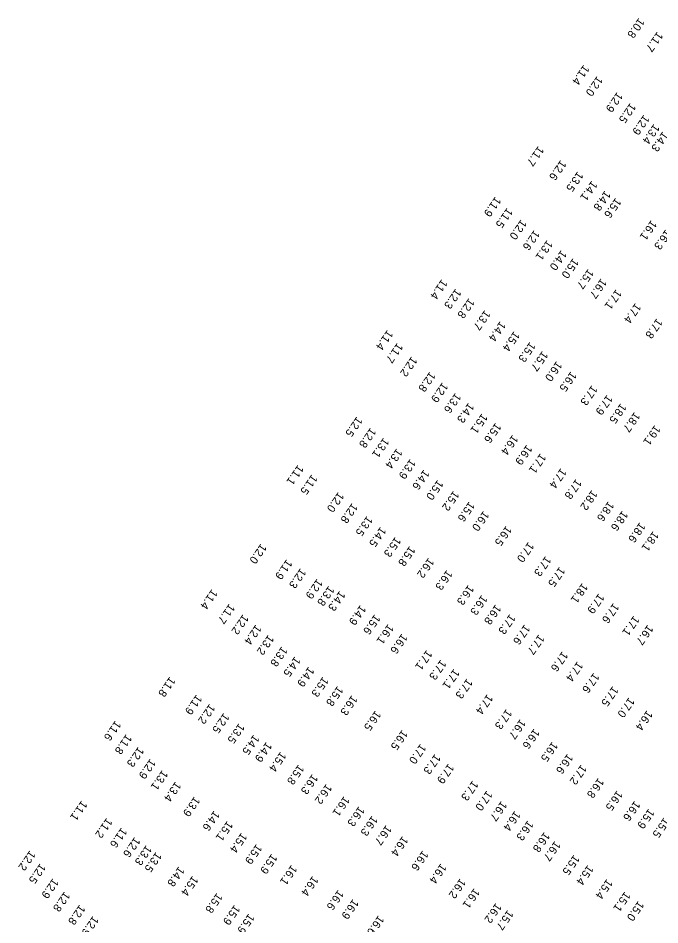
# Model space of a CAD drawing. Extents: x 815385 to 820851, y 582449 to 604245.
# Drawn here: x 816773 to 817174, y 584573 to 585139 of the extents above; entities that cross this region are included whole.
import ezdxf

# ---------------------------------------------------------------- set-up
doc = ezdxf.new("R2010")
doc.units = 0
doc.layers.add('V-TOPO-SOUN-101408', color=7, linetype='Continuous')

msp = doc.modelspace()

# ---------------------------------------------------------------- texts
at = {"layer": 'V-TOPO-SOUN-101408'}
for s, p in [('10.8 ', (817160.59, 585139.74)), ('11.7 ', (817172.12, 585131.14)), ('11.4 ', (817126.14, 585110.45)), ('12.0 ', (817134.56, 585103.43)), ('12.9 ', (817147.05, 585093.41)), ('12.5 ', (817155.23, 585086.61)), ('12.9 ', (817163.7, 585079.18)), ('13.4 ', (817170.03, 585073.49)), ('14.3 ', (817175.55, 585068.8)), ('11.7 ', (817097.75, 585059.69)), ('12.6 ', (817111.73, 585050.88)), ('13.5 ', (817122.34, 585043.79)), ('14.1 ', (817131.15, 585037.99)), ('11.9 ', (817070.92, 585028.06)), ('14.8 ', (817139.43, 585031.8)), ('15.6 ', (817146.06, 585027.28)), ('11.5 ', (817078.29, 585021.07)), ('12.0 ', (817086.97, 585013.75)), ('16.1 ', (817168.33, 585013.37)), ('12.6 ', (817095.2, 585007.17)), ('16.3 ', (817177.32, 585007.54)), ('13.1 ', (817103.24, 585000.89)), ('14.0 ', (817112.04, 584994.59)), ('15.0 ', (817119.48, 584989.57)), ('15.7 ', (817128.94, 584982.89)), ('11.4 ', (817037.46, 584976.47)), ('16.7 ', (817136.99, 584976.92)), ('12.3 ', (817046.1, 584970.55)), ('17.1 ', (817146.36, 584970.15)), ('12.8 ', (817054.4, 584964.56)), ('17.4 ', (817158.45, 584961.52)), ('13.7 ', (817064.33, 584957.14)), ('14.4 ', (817073.93, 584950.18)), ('17.8 ', (817171.85, 584951.97)), ('11.4 ', (817003.48, 584944.72)), ('15.4 ', (817082.62, 584943.95)), ('11.7 ', (817009.68, 584936.66)), ('15.3 ', (817092.5, 584937.22)), ('15.7 ', (817100.29, 584931.53)), ('12.2 ', (817018.59, 584928.15)), ('16.0 ', (817109.15, 584925.21)), ('12.8 ', (817030.01, 584918.65)), ('16.5 ', (817118.14, 584918.82)), ('12.9 ', (817037.85, 584911.97)), ('17.3 ', (817131.22, 584910.18)), ('13.6 ', (817045.99, 584905.37)), ('17.9 ', (817140.71, 584904.19)), ('14.3 ', (817054.15, 584899.25)), ('18.5 ', (817149.27, 584898.91)), ('15.1 ', (817062.55, 584892.55)), ('18.7 ', (817157.87, 584893.44)), ('12.5 ', (816984.36, 584890.6)), ('15.6 ', (817071.08, 584886.72)), ('12.8 ', (816992.92, 584883.66)), ('19.1 ', (817170.55, 584885.26)), ('13.1 ', (817001.07, 584877.37)), ('16.4 ', (817081.68, 584879.16)), ('13.4 ', (817009.3, 584870.67)), ('16.9 ', (817090.48, 584872.95)), ('13.9 ', (817017.72, 584864.13)), ('17.1 ', (817099.07, 584867.62)), ('11.1 ', (816947.62, 584860.42)), ('14.6 ', (817026.23, 584857.45)), ('17.4 ', (817111.86, 584858.35)), ('11.5 ', (816956.25, 584854.44)), ('17.8 ', (817121.33, 584851.6)), ('15.0 ', (817034.86, 584851.03)), ('12.0 ', (816972.82, 584843.44)), ('15.2 ', (817044.82, 584844.28)), ('18.2 ', (817131.2, 584844.68)), ('12.8 ', (816981.42, 584836.52)), ('15.6 ', (817054.57, 584837.49)), ('18.6 ', (817141.56, 584837.68)), ('16.0 ', (817063.53, 584831.65)), ('18.6 ', (817150.28, 584831.78)), ('13.5 ', (816990.77, 584828.52)), ('18.6 ', (817161.14, 584824.47)), ('14.5 ', (816999.18, 584821.75)), ('16.5 ', (817077.7, 584822.37)), ('18.1 ', (817169.52, 584818.98)), ('15.3 ', (817008.41, 584815.41)), ('17.0 ', (817091.55, 584812.15)), ('12.0 ', (816924.46, 584811.19)), ('15.8 ', (817017.38, 584809.69)), ('11.9 ', (816940.5, 584801.35)), ('16.2 ', (817029.16, 584802.32)), ('17.3 ', (817102.3, 584803.41)), ('12.3 ', (816949.16, 584795.8)), ('17.5 ', (817111.02, 584796.74)), ('12.9 ', (816959.53, 584789.22)), ('16.3 ', (817040.6, 584794.73)), ('13.8 ', (816966.8, 584784.81)), ('16.3 ', (817054.04, 584785.39)), ('18.1 ', (817125.23, 584786.57)), ('11.4 ', (816893.81, 584782.71)), ('14.3 ', (816973.64, 584781.68)), ('16.3 ', (817062.43, 584779.11)), ('17.9 ', (817135.49, 584780.03)), ('11.7 ', (816904.66, 584773.62)), ('14.9 ', (816986.56, 584772.84)), ('16.8 ', (817071.06, 584773.17)), ('17.6 ', (817144.73, 584774.06)), ('12.2 ', (816913.22, 584766.98)), ('15.6 ', (816995.53, 584767)), ('17.3 ', (817079.98, 584767.17)), ('16.1 ', (817003.89, 584760.9)), ('17.1 ', (817157.41, 584766.16)), ('12.4 ', (816921.24, 584760.59)), ('17.6 ', (817089.17, 584760.66)), ('16.7 ', (817166.08, 584760.45)), ('13.2 ', (816929.06, 584754.19)), ('16.6 ', (817012.52, 584754.95)), ('17.7 ', (817098.07, 584754.42)), ('13.8 ', (816937.49, 584746.92)), ('17.1 ', (817028, 584744.73)), ('17.6 ', (817112.76, 584743.87)), ('14.5 ', (816945.63, 584740.63)), ('17.3 ', (817036.77, 584738.63)), ('14.9 ', (816954.25, 584734.27)), ('17.1 ', (817045.05, 584732.93)), ('17.4 ', (817122.21, 584737.58)), ('11.8 ', (816867.47, 584728)), ('15.3 ', (816963.17, 584727.97)), ('17.3 ', (817053.19, 584726.86)), ('17.6 ', (817132.37, 584730.44)), ('15.8 ', (816972.34, 584722.23)), ('17.5 ', (817144.28, 584722.11)), ('11.9 ', (816884.15, 584716.85)), ('16.3 ', (816981.24, 584716.45)), ('17.4 ', (817065.9, 584717.09)), ('12.2 ', (816892.35, 584711.03)), ('17.0 ', (817154.4, 584715.09)), ('12.5 ', (816901.2, 584705.31)), ('16.5 ', (816995.97, 584706.88)), ('17.3 ', (817077.8, 584707.77)), ('16.4 ', (817165.67, 584707.01)), ('11.6 ', (816833.5, 584700.6)), ('13.5 ', (816910.72, 584698.9)), ('16.7 ', (817086.47, 584701.54)), ('16.5 ', (817012.69, 584694.8)), ('16.6 ', (817095.09, 584695.52)), ('11.8 ', (816840.31, 584692.11)), ('14.5 ', (816919.95, 584691.83)), ('14.9 ', (816927.81, 584687.24)), ('16.5 ', (817106.49, 584687.45)), ('12.3 ', (816847.83, 584684.19)), ('17.0 ', (817024.16, 584686.1)), ('12.9 ', (816855.26, 584676.71)), ('15.4 ', (816936.72, 584681.17)), ('17.3 ', (817033.2, 584679.72)), ('16.6 ', (817116.02, 584679.91)), ('15.8 ', (816947.92, 584673.13)), ('17.9 ', (817041.6, 584673.74)), ('17.2 ', (817124.54, 584673.08)), ('13.1 ', (816862.81, 584669.66)), ('16.3 ', (816956.54, 584667.12)), ('16.8 ', (817135.27, 584664.75)), ('13.4 ', (816871.07, 584662.5)), ('16.2 ', (816965.29, 584661.01)), ('17.3 ', (817056.73, 584663.12)), ('16.1 ', (816976.38, 584653.33)), ('17.0 ', (817065.59, 584656.86)), ('16.5 ', (817146.97, 584656.9)), ('11.1 ', (816812.42, 584650.63)), ('13.9 ', (816882.88, 584653.17)), ('16.7 ', (817074.67, 584650.32)), ('16.6 ', (817157.95, 584650.44)), ('14.6 ', (816895.18, 584644.3)), ('16.3 ', (816985.67, 584647.04)), ('16.4 ', (817083.1, 584644.17)), ('15.9 ', (817166.77, 584645.59)), ('11.2 ', (816828.07, 584639.77)), ('15.1 ', (816903.43, 584637.87)), ('16.3 ', (816993.89, 584641.12)), ('16.3 ', (817091.21, 584638.2)), ('15.5 ', (817176.29, 584639.97)), ('11.6 ', (816837.29, 584633.72)), ('15.4 ', (816912.26, 584630.54)), ('16.7 ', (817002.67, 584635.28)), ('16.8 ', (817101.49, 584630.95)), ('12.6 ', (816845.53, 584627.77)), ('16.4 ', (817012.92, 584628.39)), ('16.7 ', (817108.14, 584625.36)), ('12.2 ', (816780.04, 584619.4)), ('13.3 ', (816852.78, 584622.74)), ('15.9 ', (816921.64, 584623.42)), ('16.6 ', (817025.53, 584619.39)), ('13.5 ', (816858.9, 584618.47)), ('15.9 ', (816931.13, 584617.33)), ('15.5 ', (817120.03, 584616.69)), ('12.5 ', (816786.53, 584611.34)), ('14.8 ', (816873.13, 584609.43)), ('16.1 ', (816943.53, 584610.38)), ('16.4 ', (817036.85, 584611.27)), ('15.4 ', (817128.7, 584610.34)), ('15.4 ', (816881.75, 584603.6)), ('16.4 ', (816956.79, 584603.51)), ('12.9 ', (816794.47, 584602.02)), ('16.2 ', (817048.97, 584601.98)), ('15.4 ', (817140.64, 584601.61)), ('12.8 ', (816801.7, 584593.75)), ('15.8 ', (816896.92, 584592.87)), ('16.6 ', (816972.68, 584594.77)), ('16.1 ', (817057.66, 584595.82)), ('15.1 ', (817151.84, 584593.72)), ('12.8 ', (816811.15, 584585.53)), ('15.9 ', (816907.91, 584585.42)), ('16.9 ', (816981.96, 584589.06)), ('16.2 ', (817071.28, 584586.62)), ('15.0 ', (817160.27, 584587.93)), ('15.9 ', (816916.85, 584579.99)), ('15.7 ', (817078.64, 584582.24)), ('12.9 ', (816819.54, 584578.51)), ('16.6 ', (816997.89, 584578.88))]:
    msp.add_text(s, height=5, rotation=234.911, dxfattribs=at).set_placement(p)

doc.saveas('drawing.dxf')
